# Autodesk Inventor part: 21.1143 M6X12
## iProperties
Created: 2006-02
Part Number: 21.1143 M6X12
Material: Steel, Mild
Description: Cylinder Head Cap Screw
Document SubType Name: Modeling
Standard: DIN 7984
Designer: Andy Moles
Standards Organization: DIN
Language: en-US
Size Designation: M6 x 12
Categories: <MemberInstance><Categories><Category DisplayName="Fasteners" InternalName="e4da775c-781d-43d5-af7c-5136215cf5a6" Mnemonic="FSTN"><Category DisplayName="Bolts"
Density: 7.86 g/cm^3
Mass: 4.70792 g
Surface Area: 5.38764 cm^2
Volume: 0.598972 cm^3
Author: Andy Moles
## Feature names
1. Body [Revolution]
2. Slot [Extrusion]
3. Fillet1
4. Chamfer1
